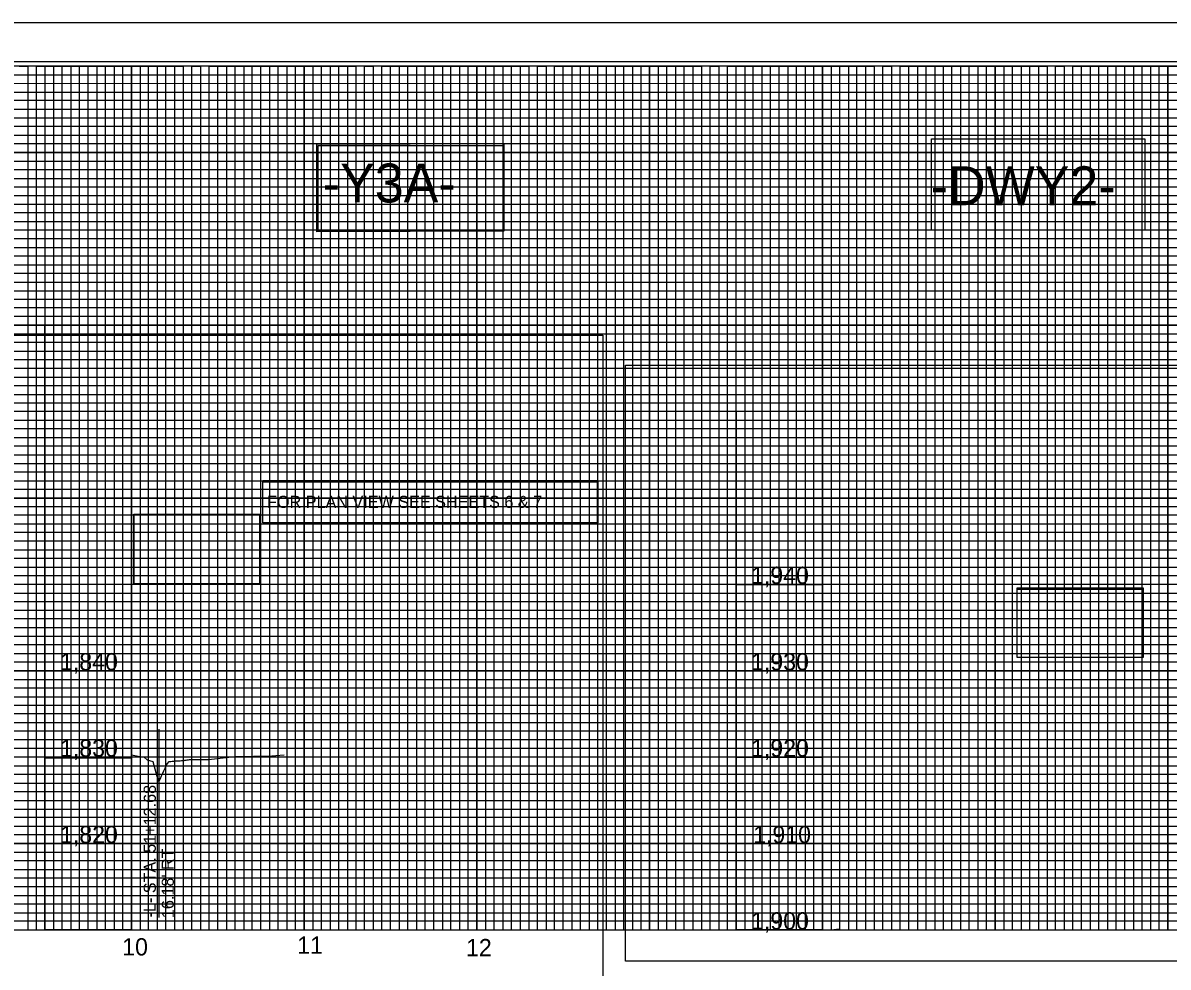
# Model space of a CAD drawing. Extents: x 557032 to 558930, y 525869 to 527437.
# Drawn here: x 557587 to 558250, y 526423 to 526969 of the extents above; entities that cross this region are included whole.
import ezdxf

# ---------------------------------------------------------------- set-up
doc = ezdxf.new("R2010")
doc.units = 0
for name, color, linetype in [('Exist Vertical Profile Ground Line', 7, 'Continuous'), ('Exist Vertical Profile Horizontal Axis Label Major', 7, 'Continuous'), ('Exist Vertical Profile Vertical Axis Label', 7, 'Continuous'), ('Old_Level_63', 7, 'Continuous'), ('Prop Vertical Profile Curve Label', 7, 'Continuous'), ('Prop Vertical Profile Grade Label', 7, 'Continuous'), ('Prop VPI Label', 7, 'Continuous'), ('Raster_Level_4', 7, 'Continuous'), ('Sheet Cutting Line CELL', 7, 'Continuous'), ('Sheet DOT Grid CELL', 7, 'Continuous'), ('Sheet Layout Profile Border Port 1', 7, 'Continuous'), ('Sheet Plot Border Inside CELL', 7, 'Continuous'), ('Sheet Plot Border Outside CELL', 7, 'Continuous'), ('Sheet Profile CELL', 7, 'Continuous'), ('Sheet Profile Grid Major CELL', 7, 'Continuous'), ('Sheet Profile Grid Middle CELL', 7, 'Continuous'), ('Sheet Profile Grid Minor CELL', 7, 'Continuous')]:
    doc.layers.add(name, color=color, linetype=linetype)

msp = doc.modelspace()

# ---------------------------------------------------------------- linework, layer by layer
at = {"layer": 'Exist Vertical Profile Ground Line'}
msp.add_lwpolyline([(557649.42, 526545.56), (557655.28, 526544.47), (557656.75, 526544.24), (557658.61, 526542.73), (557661.78, 526541.81), (557664.85, 526531.02), (557665.35, 526530.1), (557666.21, 526531.96), (557666.89, 526533.44), (557667.56, 526534.92), (557668.24, 526536.4), (557668.92, 526537.88), (557669.6, 526539.36), (557670.28, 526540.56), (557671.32, 526541.72), (557671.64, 526541.74), (557672.32, 526541.8), (557673, 526541.85), (557673.68, 526541.9), (557674.35, 526541.96), (557675.03, 526542.01), (557675.71, 526542.05), (557676.39, 526542.1), (557677.07, 526542.15), (557677.75, 526542.19), (557678.43, 526542.24), (557679.11, 526542.28), (557680.08, 526542.33), (557680.47, 526542.4), (557681.15, 526542.51), (557681.82, 526542.62), (557682.5, 526542.72), (557683.18, 526542.83), (557683.86, 526542.93), (557684.54, 526542.93), (557685.22, 526542.93), (557685.9, 526542.94), (557686.58, 526542.94), (557687.26, 526542.94), (557687.94, 526542.94), (557688.61, 526542.94), (557689.29, 526542.93), (557689.97, 526542.93), (557690.65, 526542.93), (557691.33, 526542.93), (557692.01, 526542.94), (557692.69, 526542.94), (557693.37, 526542.93), (557694.17, 526542.93), (557709.3, 526544.53), (557709.78, 526544.54), (557710.37, 526544.59), (557720.08, 526544.75), (557727.05, 526544.77), (557727.49, 526544.73), (557728.25, 526544.78), (557737.97, 526545.5)], dxfattribs=at)
at = {"layer": 'Old_Level_63'}
for points in [[(557599.32, 526794.27), (557649.32, 526794.27), (557649.32, 526444.27), (557599.32, 526444.27)], [(557999.45, 526794.22), (558049.45, 526794.22), (558049.45, 526444.22), (557999.45, 526444.22)]]:
    msp.add_lwpolyline(points, close=True, dxfattribs=at)
at = {"layer": 'Prop Vertical Profile Curve Label'}
for points in [[(558112.59, 526902.18), (558236.16, 526902.18), (558236.16, 526849.22), (558112.59, 526849.22)], [(557757.55, 526898.35), (557864.99, 526898.35), (557864.99, 526848.6), (557757.55, 526848.6)], [(557651.07, 526684.47), (557723.64, 526684.47), (557723.64, 526644.64), (557651.07, 526644.64)], [(558162.13, 526641.53), (558235.19, 526641.53), (558235.19, 526601.91), (558162.13, 526601.91)]]:
    msp.add_lwpolyline(points, close=True, dxfattribs=at)
at = {"layer": 'Prop VPI Label'}
msp.add_line((557665.6, 526451.36), (557665.6, 526560.48), dxfattribs=at)
for points in [[(557756.86, 526898.99), (557865.1, 526899.45), (557865.1, 526848.72), (557756.86, 526848.26)], [(558112.59, 526902.18), (558236.16, 526902.18), (558236.16, 526849.22), (558112.59, 526849.22)], [(557725.58, 526704.44), (557919.52, 526704.44), (557919.52, 526679.94), (557725.58, 526679.94)], [(557725.58, 526703.58), (557919.14, 526703.58), (557919.14, 526679.94), (557725.58, 526679.94)], [(557650.82, 526684.86), (557723.87, 526684.86), (557723.87, 526644.46), (557650.82, 526644.46)], [(558162.13, 526642.31), (558235.19, 526642.31), (558235.19, 526601.91), (558162.13, 526601.91)]]:
    msp.add_lwpolyline(points, close=True, dxfattribs=at)
at = {"layer": 'Raster_Level_4'}
for points in [[(557512.44, 526788.54), (557922.28, 526788.54), (557922.28, 526375.72), (557512.44, 526375.72)], [(557935.56, 526771.15), (558341.36, 526771.15), (558341.36, 526426.21), (557935.56, 526426.21)]]:
    msp.add_lwpolyline(points, close=True, dxfattribs=at)
at = {"layer": 'Sheet Cutting Line CELL'}
msp.add_line((558716.45, 526969.22), (557032.45, 526969.22), dxfattribs=at)
at = {"layer": 'Sheet DOT Grid CELL'}
for p, q in [((557599.45, 526444.22), (557599.45, 526944.22)), ((557649.45, 526444.22), (557649.45, 526944.22)), ((557699.45, 526444.22), (557699.45, 526944.22)), ((557749.45, 526444.22), (557749.45, 526944.22)), ((557799.45, 526444.22), (557799.45, 526944.22)), ((557849.45, 526444.22), (557849.45, 526944.22)), ((557899.45, 526444.22), (557899.45, 526944.22)), ((557949.45, 526444.22), (557949.45, 526944.22)), ((557999.45, 526444.22), (557999.45, 526944.22)), ((558049.45, 526444.22), (558049.45, 526944.22)), ((558099.45, 526444.22), (558099.45, 526944.22)), ((558149.45, 526444.22), (558149.45, 526944.22)), ((558199.45, 526444.22), (558199.45, 526944.22)), ((558249.45, 526444.22), (558249.45, 526944.22)), ((558499.4, 526894.22), (557199.45, 526894.22)), ((558499.4, 526844.22), (557199.45, 526844.22)), ((558499.45, 526794.22), (557199.45, 526794.22)), ((558699.45, 526694.22), (557199.45, 526694.22)), ((558699.45, 526644.22), (557199.45, 526644.22)), ((558699.45, 526594.22), (557199.45, 526594.22)), ((558699.45, 526544.22), (557199.45, 526544.22)), ((558699.45, 526494.22), (557199.45, 526494.22))]:
    msp.add_line(p, q, dxfattribs=at)
at = {"layer": 'Sheet Layout Profile Border Port 1'}
msp.add_lwpolyline([(557249.45, 526783.17), (557249.45, 526444.22), (558649.45, 526444.22), (558649.45, 526783.17)], dxfattribs=at)
at = {"layer": 'Sheet Plot Border Inside CELL'}
msp.add_lwpolyline([(557045.45, 525891.67), (558711.95, 525891.67), (558711.95, 526946.77), (557045.45, 526946.77)], close=True, dxfattribs=at)
at = {"layer": 'Sheet Plot Border Outside CELL'}
msp.add_lwpolyline([(557032.45, 525869.22), (558716.45, 525869.22), (558716.45, 526969.22), (557032.45, 526969.22)], close=True, dxfattribs=at)
at = {"layer": 'Sheet Profile CELL'}
msp.add_line((557199.45, 526444.22), (558699.45, 526444.22), dxfattribs=at)
msp.add_lwpolyline([(558699.45, 526944.22), (557199.45, 526944.22), (557199.45, 525894.22), (558699.45, 525894.22)], close=True, dxfattribs=at)
at = {"layer": 'Sheet Profile Grid Major CELL'}
for p, q in [((557749.45, 526694.22), (557799.45, 526694.22)), ((557999.45, 526694.22), (558049.45, 526694.22)), ((557999.45, 526644.22), (558049.45, 526644.22)), ((557999.45, 526644.22), (558049.45, 526644.22)), ((557599.55, 526594.13), (557649.55, 526594.13)), ((557999.45, 526594.22), (558049.45, 526594.22)), ((557999.45, 526594.22), (558049.45, 526594.22)), ((557599.55, 526543.81), (557649.55, 526543.81)), ((557999.45, 526544.22), (558049.45, 526544.22)), ((557999.45, 526544.22), (558049.45, 526544.22)), ((557598.82, 526494.21), (557648.82, 526494.21)), ((557999.45, 526494.22), (558049.45, 526494.22)), ((557999.45, 526494.22), (558049.45, 526494.22))]:
    msp.add_line(p, q, dxfattribs=at)
for points in [[(557549.45, 526444.22), (557599.45, 526444.22), (557599.45, 526944.22), (557649.45, 526944.22), (557649.45, 526444.22), (557699.45, 526444.22), (557699.45, 526944.22), (557749.45, 526944.22), (557749.45, 526444.22), (557799.45, 526444.22), (557799.45, 526944.22), (557849.45, 526944.22), (557849.45, 526444.22), (557899.45, 526444.22), (557899.45, 526944.22), (557949.45, 526944.22), (557949.45, 526444.22), (557999.45, 526444.22), (557999.45, 526944.22), (558049.45, 526944.22), (558049.45, 526444.22), (558099.45, 526444.22), (558099.45, 526944.22), (558149.45, 526944.22), (558149.45, 526444.22), (558199.45, 526444.22), (558199.45, 526944.22), (558249.45, 526944.22), (558249.45, 526444.22), (558299.45, 526444.22)], [(557199.45, 526894.22), (558499.45, 526894.22)], [(558499.45, 526844.22), (557199.45, 526844.22), (557199.45, 526794.22), (558499.45, 526794.22)], [(558699.45, 526744.22), (557199.45, 526744.22), (557199.45, 526694.22), (558699.45, 526694.22)], [(558699.45, 526644.22), (557199.45, 526644.22), (557199.45, 526594.22), (558699.45, 526594.22)], [(558699.45, 526544.22), (557199.45, 526544.22), (557199.45, 526544.22), (557199.45, 526494.22), (558699.45, 526494.22)]]:
    msp.add_lwpolyline(points, dxfattribs=at)
for points in [[(557749.45, 526444.22), (557799.45, 526444.22), (557799.45, 526744.22), (557749.45, 526744.22)], [(557999.45, 526444.22), (558049.45, 526444.22), (558049.45, 526744.22), (557999.45, 526744.22)]]:
    msp.add_lwpolyline(points, close=True, dxfattribs=at)
at = {"layer": 'Sheet Profile Grid Middle CELL'}
msp.add_line((557199.45, 526919.22), (558499.4, 526919.22), dxfattribs=at)
for points in [[(557574.45, 526444.22), (557624.45, 526444.22), (557624.45, 526944.22), (557674.45, 526944.22), (557674.45, 526444.22), (557724.45, 526444.22), (557724.45, 526944.22), (557774.45, 526944.22), (557774.45, 526444.22), (557824.45, 526444.22), (557824.45, 526444.22), (557824.45, 526944.22), (557874.45, 526944.22), (557874.45, 526444.22), (557924.45, 526444.22), (557924.45, 526944.22), (557974.45, 526944.22), (557974.45, 526444.22), (558024.45, 526444.22), (558024.45, 526944.22), (558074.45, 526944.22), (558074.45, 526444.22), (558124.45, 526444.22), (558124.45, 526944.22), (558174.45, 526944.22), (558174.45, 526444.22), (558224.45, 526444.22), (558224.45, 526944.22), (558274.45, 526944.22)], [(558499.45, 526869.22), (557199.45, 526869.22), (557199.45, 526819.22), (558499.45, 526819.22)], [(558699.45, 526769.22), (557199.45, 526769.22), (557199.45, 526719.22), (558524.45, 526719.22)], [(558699.45, 526669.22), (557199.45, 526669.22), (557199.45, 526619.22), (558699.45, 526619.22)], [(558699.45, 526569.22), (557199.45, 526569.22), (557199.45, 526519.22), (558699.45, 526519.22)], [(558699.45, 526469.22), (557199.45, 526469.22)]]:
    msp.add_lwpolyline(points, dxfattribs=at)
at = {"layer": 'Sheet Profile Grid Minor CELL'}
for p, q in [((557249.45, 526939.22), (558499.45, 526939.22)), ((558499.45, 526934.22), (557249.45, 526933.87)), ((557249.45, 526929.22), (558499.45, 526929.22)), ((558499.4, 526809.22), (557249.45, 526809.22)), ((558499.45, 526804.22), (557249.45, 526804.22)), ((558499.45, 526799.22), (557249.45, 526799.22)), ((557249.45, 526789.22), (558499.45, 526789.22)), ((558499.45, 526784.22), (557249.45, 526784.22)), ((557249.45, 526779.22), (558649.45, 526779.22)), ((558649.45, 526759.22), (557249.45, 526759.22)), ((557249.45, 526754.22), (558649.45, 526754.22)), ((558649.45, 526734.22), (557249.45, 526734.22)), ((557249.45, 526729.22), (558649.45, 526729.22)), ((558649.45, 526709.22), (557249.45, 526709.22)), ((557249.45, 526704.22), (558649.45, 526704.22)), ((558649.45, 526699.22), (557249.45, 526699.22)), ((557249.45, 526689.22), (558649.45, 526689.22)), ((558649.45, 526684.22), (557249.45, 526684.22)), ((557249.45, 526679.22), (558649.45, 526679.22)), ((558649.45, 526674.22), (557249.45, 526674.22)), ((557249.45, 526664.22), (558649.45, 526664.22)), ((558649.45, 526659.22), (557249.45, 526659.22)), ((557249.45, 526654.22), (558649.45, 526654.22)), ((558649.45, 526649.22), (557249.45, 526649.22)), ((557249.45, 526639.22), (558649.45, 526639.22)), ((558649.45, 526634.22), (557249.45, 526634.22)), ((557249.45, 526629.22), (558649.45, 526629.22)), ((558649.45, 526624.22), (557249.45, 526624.22)), ((557249.45, 526614.22), (558649.45, 526614.22)), ((558649.45, 526609.22), (557249.45, 526609.22)), ((557249.45, 526604.22), (558649.45, 526604.22)), ((558649.45, 526599.22), (557249.45, 526599.22)), ((557249.45, 526589.22), (558649.45, 526589.22)), ((558649.45, 526584.22), (557249.45, 526584.22)), ((557249.45, 526579.22), (558649.45, 526579.22)), ((558649.45, 526574.22), (557249.45, 526574.22)), ((557249.45, 526564.22), (558649.45, 526564.22)), ((558649.45, 526559.22), (557249.45, 526559.22)), ((558649.45, 526554.22), (557249.45, 526554.22)), ((558649.45, 526549.22), (557249.45, 526549.22)), ((557249.45, 526539.22), (558649.45, 526539.22)), ((558649.45, 526534.22), (557249.45, 526534.22)), ((557249.45, 526529.22), (558649.45, 526529.22)), ((558649.45, 526524.22), (557249.45, 526524.22)), ((557249.45, 526514.22), (558649.45, 526514.22)), ((558649.45, 526509.22), (557249.45, 526509.22)), ((557249.45, 526504.22), (558649.45, 526504.22)), ((558649.45, 526499.22), (557249.45, 526499.22)), ((557249.45, 526489.22), (558649.45, 526489.22)), ((558649.45, 526484.22), (557249.45, 526484.22)), ((557249.45, 526479.22), (558649.45, 526479.22)), ((558649.45, 526474.22), (557249.45, 526474.22)), ((557249.45, 526464.22), (558649.45, 526464.22)), ((558649.45, 526459.22), (557249.45, 526459.22)), ((557249.45, 526454.22), (558649.45, 526454.22))]:
    msp.add_line(p, q, dxfattribs=at)
for points in [[(557584.45, 526944.22), (557589.45, 526944.22), (557589.45, 526444.22), (557594.45, 526444.22), (557594.45, 526944.22), (557604.45, 526944.22), (557604.45, 526444.22), (557609.45, 526444.22), (557609.45, 526944.22), (557614.45, 526944.22), (557614.45, 526444.22), (557619.45, 526444.22), (557619.45, 526944.22), (557629.45, 526944.22), (557629.45, 526444.22), (557634.45, 526444.22), (557634.45, 526944.22), (557639.45, 526944.22), (557639.45, 526444.22), (557644.45, 526444.22), (557644.45, 526944.22), (557654.45, 526944.22), (557654.45, 526444.22), (557659.45, 526444.22), (557659.45, 526944.22), (557664.45, 526944.22), (557664.45, 526444.22), (557669.45, 526444.22), (557669.45, 526944.22), (557679.45, 526944.22), (557679.45, 526444.22), (557684.45, 526444.22), (557684.45, 526944.22), (557689.45, 526944.22), (557689.45, 526444.22), (557694.45, 526444.22), (557694.45, 526944.22), (557704.45, 526944.22), (557704.45, 526444.22), (557709.45, 526444.22), (557709.45, 526944.22), (557714.45, 526944.22), (557714.45, 526444.22), (557719.45, 526444.22), (557719.45, 526944.22), (557729.45, 526944.22), (557729.45, 526444.22), (557734.45, 526444.22), (557734.45, 526944.22), (557739.45, 526944.22), (557739.45, 526444.22), (557744.45, 526444.22), (557744.45, 526944.22), (557754.45, 526944.22), (557754.45, 526444.22), (557759.45, 526444.22), (557759.45, 526944.22), (557764.45, 526944.22), (557764.45, 526444.22), (557769.45, 526444.22), (557769.45, 526944.22), (557779.45, 526944.22)], [(557779.45, 526944.22), (557779.45, 526444.22), (557784.45, 526444.22), (557784.45, 526944.22), (557789.45, 526944.22), (557789.45, 526444.22), (557794.45, 526444.22), (557794.45, 526944.22), (557804.45, 526944.22), (557804.45, 526444.22), (557809.45, 526444.22), (557809.45, 526944.22), (557814.45, 526944.22), (557814.45, 526444.22), (557819.45, 526444.22), (557819.45, 526944.22), (557829.45, 526944.22), (557829.45, 526444.22), (557834.45, 526444.22), (557834.45, 526944.22), (557839.45, 526944.22), (557839.45, 526444.22), (557844.45, 526444.22), (557844.45, 526944.22), (557854.45, 526944.22), (557854.45, 526444.22), (557859.45, 526444.22), (557859.45, 526944.22), (557864.45, 526944.22), (557864.45, 526444.22), (557869.45, 526444.22), (557869.45, 526944.22), (557879.45, 526944.22), (557879.45, 526444.22), (557884.45, 526444.22), (557884.45, 526944.22), (557889.45, 526944.22), (557889.45, 526444.22), (557894.45, 526444.22), (557894.45, 526944.22), (557904.45, 526944.22), (557904.45, 526444.22), (557904.45, 526444.22), (557909.45, 526444.22), (557909.45, 526944.22), (557914.45, 526944.22), (557914.45, 526444.22), (557919.45, 526444.22), (557919.45, 526944.22), (557929.45, 526944.22), (557929.45, 526444.22), (557934.45, 526444.22), (557934.45, 526944.22), (557939.45, 526944.22), (557939.45, 526444.22), (557944.45, 526444.22), (557944.45, 526944.22), (557954.45, 526944.22), (557954.45, 526444.22), (557959.45, 526444.22), (557959.45, 526944.22), (557964.45, 526944.22), (557964.45, 526444.22), (557969.45, 526444.22), (557969.45, 526944.22), (557979.45, 526944.22), (557979.45, 526444.22), (557984.45, 526444.22), (557984.45, 526944.22), (557989.45, 526944.22), (557989.45, 526444.22), (557994.45, 526444.22), (557994.45, 526944.22), (558004.45, 526944.22), (558004.45, 526444.22), (558009.45, 526444.22), (558009.45, 526944.22), (558014.45, 526944.22), (558014.45, 526444.22), (558019.45, 526444.22), (558019.45, 526944.22), (558029.45, 526944.22), (558029.45, 526444.22), (558034.45, 526444.22), (558034.45, 526944.22), (558039.45, 526944.22), (558039.45, 526444.22), (558044.45, 526444.22), (558044.45, 526944.22), (558054.45, 526944.22), (558054.45, 526444.22), (558059.15, 526444.77), (558059.45, 526444.22), (558059.45, 526944.22), (558064.45, 526944.22), (558064.45, 526444.22), (558069.45, 526444.22), (558069.45, 526944.22), (558079.45, 526944.22), (558079.45, 526444.22), (558084.45, 526444.22)], [(558084.45, 526444.22), (558084.45, 526944.22), (558089.45, 526944.22), (558089.45, 526444.22), (558094.45, 526444.22), (558094.45, 526944.22), (558104.45, 526944.22), (558104.45, 526444.22), (558109.45, 526444.22), (558109.45, 526944.22), (558114.45, 526944.22), (558114.45, 526444.22), (558119.45, 526444.22), (558119.45, 526944.22), (558129.45, 526944.22), (558129.45, 526444.22), (558134.45, 526444.22), (558134.45, 526944.22), (558139.45, 526944.22), (558139.45, 526444.22), (558144.45, 526444.22), (558144.45, 526944.22), (558154.45, 526944.22), (558154.45, 526444.22), (558159.45, 526444.22), (558159.45, 526944.22), (558164.45, 526944.22), (558164.45, 526444.22), (558169.45, 526444.22), (558169.45, 526944.22), (558179.45, 526944.22), (558179.45, 526444.22), (558184.45, 526444.22), (558184.45, 526944.22), (558189.45, 526944.22), (558189.45, 526444.22), (558194.45, 526444.22), (558194.45, 526944.22), (558204.45, 526944.22), (558204.45, 526444.22), (558209.45, 526444.22), (558209.45, 526944.22), (558214.45, 526944.22), (558214.45, 526444.22), (558219.45, 526444.22), (558219.45, 526944.22), (558229.45, 526944.22), (558229.45, 526444.22), (558234.45, 526444.22), (558234.45, 526944.22), (558239.45, 526944.22), (558239.45, 526444.22), (558244.45, 526444.22), (558244.45, 526944.22), (558254.45, 526944.22)], [(558499.45, 526924.22), (557249.45, 526924.22), (557249.45, 526914.22), (558499.45, 526914.22)], [(558499.4, 526909.22), (557249.45, 526909.22), (557249.45, 526904.22), (558499.45, 526904.22)], [(558499.45, 526899.22), (557249.45, 526899.22), (557249.45, 526889.22), (558499.45, 526889.22)], [(558499.45, 526884.22), (557249.45, 526884.22), (557249.45, 526879.22), (558499.45, 526879.22)], [(558499.45, 526874.22), (557249.45, 526874.22), (557249.45, 526864.22), (558499.45, 526864.22)], [(558499.45, 526859.22), (557249.45, 526859.22), (557249.45, 526854.22), (558499.45, 526854.22)], [(558499.45, 526849.22), (557249.45, 526849.22), (557249.45, 526839.22), (558499.45, 526839.22)], [(558499.45, 526834.12), (557249.55, 526834.12), (557249.55, 526829.22), (558499.45, 526829.22)], [(558499.45, 526824.22), (557249.45, 526824.22), (557249.45, 526814.22), (558499.45, 526814.22)], [(558649.45, 526774.22), (557249.45, 526774.22), (557249.45, 526764.22), (558649.45, 526764.22)], [(558649.45, 526749.22), (557249.45, 526749.22), (557249.45, 526739.22), (558649.45, 526739.22)], [(558649.45, 526724.22), (557249.45, 526724.22), (557249.45, 526714.22), (558649.45, 526714.22)], [(558649.45, 526449.22), (557249.45, 526449.22)]]:
    msp.add_lwpolyline(points, dxfattribs=at)

# ---------------------------------------------------------------- texts
at = {"layer": 'Exist Vertical Profile Horizontal Axis Label Major'}
for s, p in [('10', (557644.15, 526429.45)), ('11', (557745.43, 526430.44)), ('12', (557843.17, 526429.01))]:
    msp.add_text(s, height=10, dxfattribs=at).set_placement(p)
at = {"layer": 'Exist Vertical Profile Vertical Axis Label'}
for s, p in [('1,940', (558008.15, 526644.47)), ('1,840', (557608.15, 526594.47)), ('1,930', (558008.15, 526594.47)), ('1,830', (557608.15, 526544.47)), ('1,920', (558008.15, 526544.47)), ('1,820', (557608.15, 526494.47)), ('1,910', (558009.35, 526494.47)), ('1,900', (558008.15, 526444.47))]:
    msp.add_text(s, height=10, dxfattribs=at).set_placement(p)
at = {"layer": 'Prop Vertical Profile Grade Label'}
for s, p in [('-Y3A-', (557760.23, 526865.3)), ('-DWY2-', (558112.18, 526863.71))]:
    msp.add_text(s, height=22.5, dxfattribs=at).set_placement(p)
at = {"layer": 'Prop VPI Label'}
msp.add_text('FOR PLAN VIEW SEE SHEETS 6 & 7', height=7, dxfattribs=at).set_placement((557728.02, 526688.5))
for s, p in [('-L- STA. 51+12.68', (557663.59, 526451.42)), ("16.18' RT", (557674.01, 526451.09))]:
    msp.add_text(s, height=7, rotation=90, dxfattribs=at).set_placement(p)

doc.saveas('drawing.dxf')
